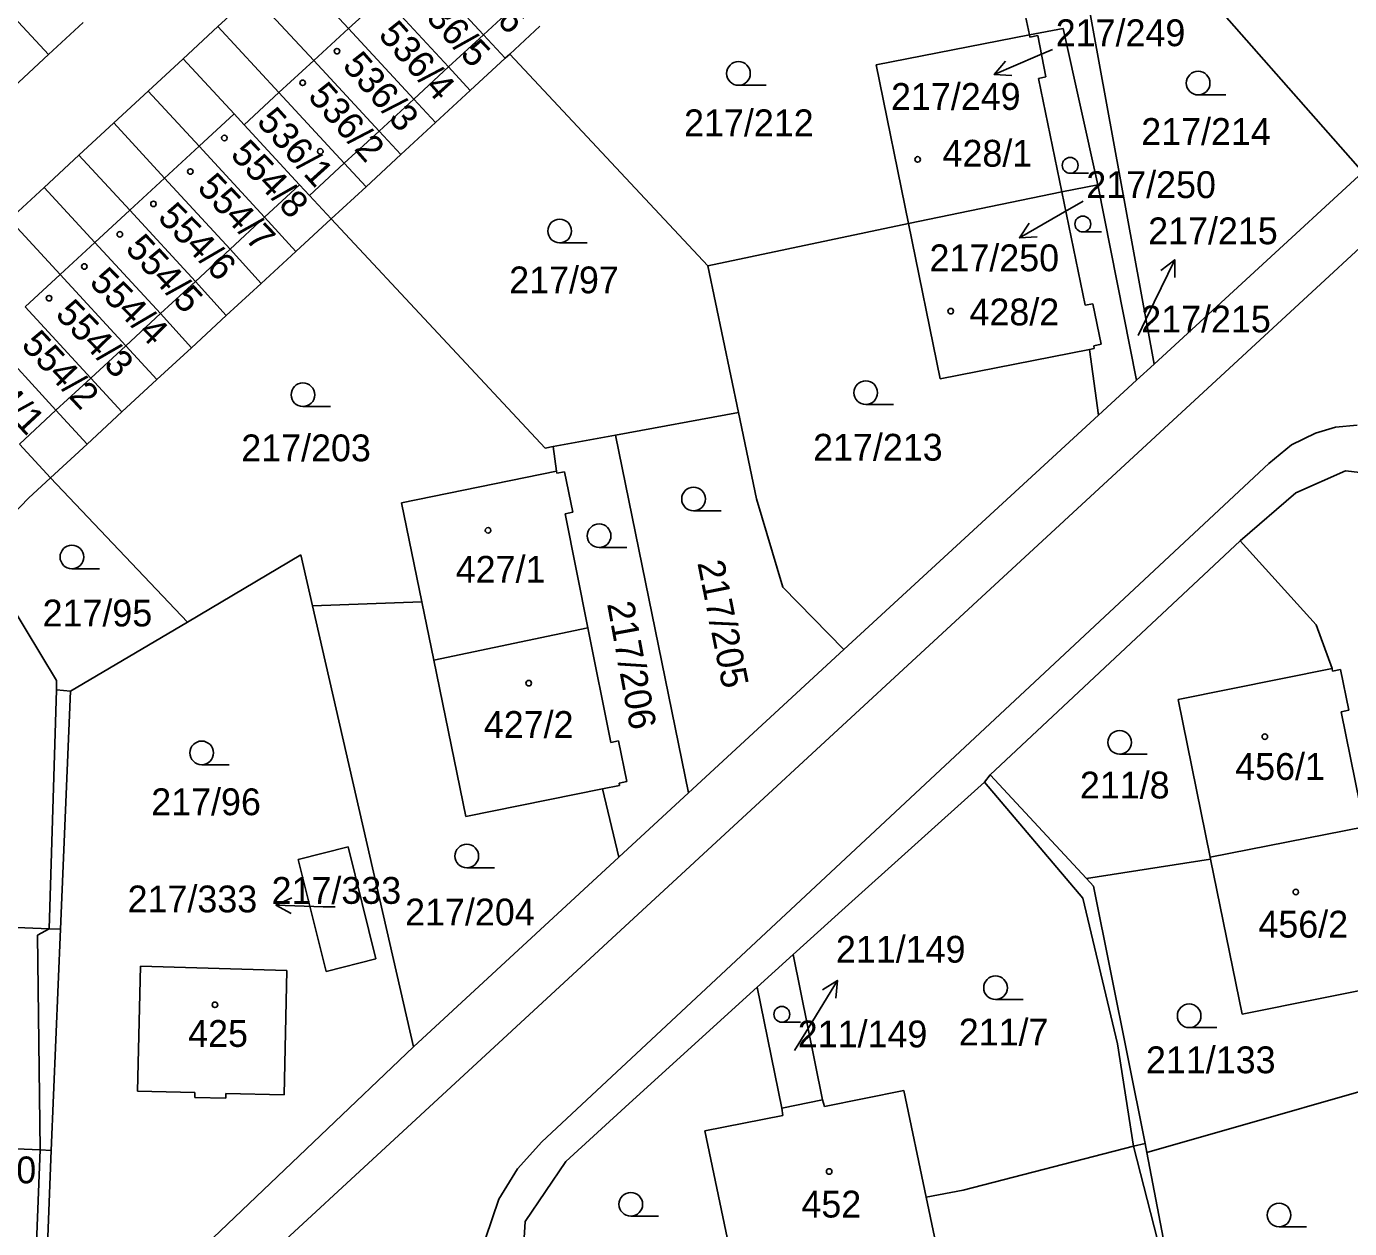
# Model space of a CAD drawing. Extents: x -735249 to -729401, y -1124843 to -1121828.
# Drawn here: x -733271.5 to -733187.6, y -1123306 to -1123229.8 of the extents above; entities that cross this region are included whole.
import ezdxf

# ---------------------------------------------------------------- set-up
doc = ezdxf.new("R2010")
doc.units = 0
for name, color, linetype in [('Vrstva 1', 7, 'Continuous'), ('Vrstva 16', 7, 'Continuous'), ('Vrstva 18', 7, 'Continuous'), ('Vrstva 19', 7, 'Continuous'), ('Vrstva 25', 7, 'Continuous'), ('Vrstva 4', 7, 'Continuous')]:
    doc.layers.add(name, color=color, linetype=linetype)

msp = doc.modelspace()

# ---------------------------------------------------------------- linework, layer by layer
at = {"layer": 'Vrstva 1'}
for points in [[(-733254.97, -1123225.7), (-733251.09, -1123229.88)], [(-733246.68, -1123225.81), (-733242.54, -1123230.29)], [(-733198.55, -1123225.62), (-733186.77, -1123238.99)], [(-733259.38, -1123229.77), (-733257.18, -1123227.74)], [(-733257.18, -1123227.74), (-733253.29, -1123231.92)], [(-733248.88, -1123227.85), (-733244.74, -1123232.33)], [(-733204.31, -1123227.55), (-733200.01, -1123251.17)], [(-733273.42, -1123227.98), (-733270.11, -1123231.54)], [(-733267.91, -1123229.51), (-733270.11, -1123231.54)], [(-733208.22, -1123228.82), (-733207.91, -1123230.3)], [(-733261.58, -1123231.81), (-733259.38, -1123229.77)], [(-733259.38, -1123229.77), (-733255.5, -1123233.95)], [(-733251.09, -1123229.88), (-733246.95, -1123234.36)], [(-733242.54, -1123230.29), (-733241.16, -1123231.78)], [(-733240.87, -1123231.52), (-733238.96, -1123229.75)], [(-733217.62, -1123232.2), (-733207.91, -1123230.3)], [(-733207.91, -1123230.3), (-733205.77, -1123229.88)], [(-733207.91, -1123230.3), (-733207.88, -1123230.44)], [(-733207.88, -1123230.44), (-733207.38, -1123230.33)], [(-733207.38, -1123230.33), (-733206.86, -1123232.95)], [(-733205.77, -1123229.88), (-733203.58, -1123239.8)], [(-733270.11, -1123231.54), (-733272.32, -1123233.58)], [(-733263.8, -1123233.86), (-733261.58, -1123231.81)], [(-733261.58, -1123231.81), (-733258.35, -1123235.3)], [(-733253.29, -1123231.92), (-733249.15, -1123236.4)], [(-733241.16, -1123231.78), (-733243.37, -1123233.81)], [(-733241.16, -1123231.78), (-733240.87, -1123231.52)], [(-733240.87, -1123231.52), (-733228.31, -1123244.94)], [(-733244.74, -1123232.33), (-733243.37, -1123233.81)], [(-733217.62, -1123232.2), (-733215.57, -1123242.25)], [(-733206.86, -1123232.95), (-733207.34, -1123233.05)], [(-733243.37, -1123233.81), (-733245.57, -1123235.85)], [(-733207.34, -1123233.05), (-733205.86, -1123240.24)], [(-733176.48, -1123234.11), (-733421.95, -1123460.73)], [(-733265.98, -1123235.88), (-733263.8, -1123233.86)], [(-733263.8, -1123233.86), (-733260.57, -1123237.35)], [(-733255.5, -1123233.95), (-733251.36, -1123238.43)], [(-733246.95, -1123234.36), (-733245.57, -1123235.85)], [(-733258.35, -1123235.3), (-733257.7, -1123235.99)], [(-733268.19, -1123237.92), (-733265.98, -1123235.88)], [(-733265.98, -1123235.88), (-733262.76, -1123239.37)], [(-733257.7, -1123235.99), (-733254.19, -1123239.8)], [(-733245.57, -1123235.85), (-733247.78, -1123237.88)], [(-733249.15, -1123236.4), (-733247.78, -1123237.88)], [(-733270.4, -1123239.97), (-733268.19, -1123237.92)], [(-733268.19, -1123237.92), (-733264.96, -1123241.41)], [(-733260.57, -1123237.35), (-733256.41, -1123241.85)], [(-733247.78, -1123237.88), (-733249.98, -1123239.92)], [(-733251.36, -1123238.43), (-733249.98, -1123239.92)], [(-733262.76, -1123239.37), (-733258.6, -1123243.88)], [(-733200.01, -1123251.17), (-733186.77, -1123238.99)], [(-733272.59, -1123242), (-733270.4, -1123239.97)], [(-733270.4, -1123239.97), (-733267.18, -1123243.46)], [(-733254.19, -1123239.8), (-733253.56, -1123240.47)], [(-733253.56, -1123240.47), (-733252.19, -1123241.95)], [(-733249.98, -1123239.92), (-733252.19, -1123241.95)], [(-733215.57, -1123242.25), (-733205.86, -1123240.24)], [(-733205.86, -1123240.24), (-733203.58, -1123239.8)], [(-733205.86, -1123240.24), (-733204.37, -1123247.44)], [(-733203.58, -1123239.8), (-733201.11, -1123252.18)], [(-733272.59, -1123242), (-733269.37, -1123245.49)], [(-733264.96, -1123241.41), (-733260.8, -1123245.92)], [(-733256.41, -1123241.85), (-733254.44, -1123244.03)], [(-733254.44, -1123244.03), (-733252.19, -1123241.95)], [(-733238.61, -1123256.49), (-733252.19, -1123241.95)], [(-733215.57, -1123242.25), (-733228.31, -1123244.94)], [(-733215.57, -1123242.25), (-733213.56, -1123252.1)], [(-733267.18, -1123243.46), (-733263.02, -1123247.97)], [(-733258.6, -1123243.88), (-733256.63, -1123246.05)], [(-733256.63, -1123246.05), (-733254.44, -1123244.03)], [(-733269.37, -1123245.49), (-733265.21, -1123250)], [(-733228.31, -1123244.94), (-733226.36, -1123254.24)], [(-733260.8, -1123245.92), (-733258.84, -1123248.08)], [(-733258.84, -1123248.08), (-733256.63, -1123246.05)], [(-733271.59, -1123247.54), (-733267.43, -1123252.05)], [(-733263.02, -1123247.97), (-733261.05, -1123250.13)], [(-733203.88, -1123247.34), (-733204.37, -1123247.44)], [(-733203.35, -1123249.91), (-733203.88, -1123247.34)], [(-733261.05, -1123250.13), (-733258.84, -1123248.08)], [(-733273.8, -1123249.57), (-733269.64, -1123254.09)], [(-733265.21, -1123250), (-733263.24, -1123252.15)], [(-733263.24, -1123252.15), (-733261.05, -1123250.13)], [(-733204.1, -1123250.24), (-733213.56, -1123252.1)], [(-733203.8, -1123250.18), (-733204.1, -1123250.24)], [(-733204.1, -1123250.24), (-733203.53, -1123254.41)], [(-733203.83, -1123250.01), (-733203.35, -1123249.91)], [(-733203.8, -1123250.18), (-733203.83, -1123250.01)], [(-733201.11, -1123252.18), (-733200.01, -1123251.17)], [(-733267.43, -1123252.05), (-733265.46, -1123254.2)], [(-733265.46, -1123254.2), (-733263.24, -1123252.15)], [(-733203.53, -1123254.41), (-733201.11, -1123252.18)], [(-733269.64, -1123254.09), (-733267.67, -1123256.24)], [(-733267.67, -1123256.24), (-733265.46, -1123254.2)], [(-733226.36, -1123254.24), (-733234.15, -1123255.67)], [(-733226.36, -1123254.24), (-733225.21, -1123259.71)], [(-733219.67, -1123269.26), (-733203.53, -1123254.41)], [(-733191.3, -1123256.29), (-733189.77, -1123255.54)], [(-733189.77, -1123255.54), (-733188.51, -1123255.16)], [(-733188.51, -1123255.16), (-733187.12, -1123255.04)], [(-733271.96, -1123256.24), (-733269.99, -1123258.38)], [(-733269.99, -1123258.38), (-733267.67, -1123256.24)], [(-733238.12, -1123256.4), (-733238.61, -1123256.49)], [(-733234.15, -1123255.67), (-733238.12, -1123256.4)], [(-733238.12, -1123256.4), (-733237.9, -1123257.95)], [(-733234.15, -1123255.67), (-733229.53, -1123278.36)], [(-733192.72, -1123257.46), (-733191.3, -1123256.29)], [(-733247.73, -1123259.96), (-733237.9, -1123257.95)], [(-733238.83, -1123300.49), (-733192.72, -1123257.46)], [(-733237.9, -1123257.95), (-733237.87, -1123258.09)], [(-733237.87, -1123258.09), (-733237.39, -1123257.99)], [(-733237.39, -1123257.99), (-733236.87, -1123260.56)], [(-733191.01, -1123259.33), (-733187.87, -1123257.94)], [(-733187.87, -1123257.94), (-733183.98, -1123258.38)], [(-733269.99, -1123258.38), (-733271.38, -1123259.66)], [(-733269.99, -1123258.38), (-733261.3, -1123267.52)], [(-733271.38, -1123259.66), (-733273.39, -1123261.75)], [(-733225.21, -1123259.71), (-733223.55, -1123265.31)], [(-733194.55, -1123262.38), (-733191.01, -1123259.33)], [(-733247.73, -1123259.96), (-733246.44, -1123266.25)], [(-733236.87, -1123260.56), (-733237.36, -1123260.66)], [(-733237.36, -1123260.66), (-733235.91, -1123267.9)], [(-733269.6, -1123271.23), (-733274.59, -1123262.99)], [(-733210.4, -1123277.22), (-733194.55, -1123262.38)], [(-733194.55, -1123262.38), (-733189.72, -1123267.69)], [(-733261.3, -1123267.52), (-733254.11, -1123263.27)], [(-733254.11, -1123263.27), (-733253.37, -1123266.49)], [(-733223.55, -1123265.31), (-733219.67, -1123269.26)], [(-733253.37, -1123266.49), (-733246.44, -1123266.25)], [(-733253.37, -1123266.49), (-733246.96, -1123294.45)], [(-733246.44, -1123266.25), (-733245.68, -1123269.93)], [(-733268.71, -1123271.9), (-733261.3, -1123267.52)], [(-733245.68, -1123269.93), (-733235.91, -1123267.9)], [(-733235.91, -1123267.9), (-733234.45, -1123275.15)], [(-733189.72, -1123267.69), (-733188.71, -1123270.47)], [(-733229.53, -1123278.36), (-733219.67, -1123269.26)], [(-733245.68, -1123269.93), (-733243.65, -1123279.86)], [(-733188.71, -1123270.47), (-733198.48, -1123272.44)], [(-733188.71, -1123270.47), (-733188.68, -1123270.63)], [(-733188.68, -1123270.63), (-733188.19, -1123270.53)], [(-733188.19, -1123270.53), (-733187.65, -1123273.11)], [(-733269.61, -1123271.82), (-733269.6, -1123271.23)], [(-733268.71, -1123271.9), (-733269.61, -1123271.82)], [(-733269.35, -1123287), (-733268.71, -1123271.9)], [(-733198.48, -1123272.44), (-733196.44, -1123282.44)], [(-733187.65, -1123273.11), (-733188.15, -1123273.21)], [(-733188.15, -1123273.21), (-733186.67, -1123280.5)], [(-733234.45, -1123275.15), (-733233.96, -1123275.05)], [(-733233.96, -1123275.05), (-733233.43, -1123277.64)], [(-733210.76, -1123277.68), (-733210.4, -1123277.22)], [(-733210.4, -1123277.22), (-733204.28, -1123283.79)], [(-733234.98, -1123278.1), (-733243.65, -1123279.86)], [(-733233.9, -1123277.88), (-733234.98, -1123278.1)], [(-733234.98, -1123278.1), (-733233.94, -1123282.43)], [(-733233.43, -1123277.64), (-733233.93, -1123277.74)], [(-733233.93, -1123277.74), (-733233.9, -1123277.88)], [(-733219.8, -1123285.82), (-733210.76, -1123277.68)], [(-733233.94, -1123282.43), (-733229.53, -1123278.36)], [(-733196.44, -1123282.44), (-733186.67, -1123280.5)], [(-733254.28, -1123282.57), (-733251.11, -1123281.78)], [(-733251.11, -1123281.78), (-733249.36, -1123288.88)], [(-733246.96, -1123294.45), (-733233.94, -1123282.43)], [(-733196.44, -1123282.44), (-733196.42, -1123282.56)], [(-733252.51, -1123289.67), (-733254.28, -1123282.57)], [(-733204.28, -1123283.79), (-733196.42, -1123282.56)], [(-733196.42, -1123282.56), (-733194.42, -1123292.39)], [(-733204.28, -1123283.79), (-733203.84, -1123284.26)], [(-733203.84, -1123284.26), (-733200.58, -1123300.58)], [(-733219.8, -1123285.82), (-733222.68, -1123288.41)], [(-733270.08, -1123286.97), (-733279.37, -1123286.59)], [(-733270.08, -1123286.97), (-733269.35, -1123287)], [(-733269.35, -1123287), (-733269.95, -1123301.03)], [(-733249.36, -1123288.88), (-733252.51, -1123289.67)], [(-733222.89, -1123288.6), (-733225.17, -1123290.67)], [(-733222.68, -1123288.41), (-733222.89, -1123288.6)], [(-733222.89, -1123288.6), (-733221.03, -1123297.82)], [(-733264.48, -1123297.27), (-733264.28, -1123289.35)], [(-733264.28, -1123289.35), (-733255, -1123289.62)], [(-733255, -1123289.62), (-733255.17, -1123297.5)], [(-733225.17, -1123290.67), (-733233.3, -1123298.05)], [(-733225.17, -1123290.67), (-733223.61, -1123298.34)], [(-733194.42, -1123292.39), (-733184.63, -1123290.43)], [(-733246.96, -1123294.45), (-733270.56, -1123316.95)], [(-733180.65, -1123295.5), (-733200.47, -1123301.15)], [(-733260.83, -1123297.36), (-733264.48, -1123297.27)], [(-733260.84, -1123297.66), (-733260.83, -1123297.36)], [(-733255.17, -1123297.5), (-733258.86, -1123297.41)], [(-733258.86, -1123297.41), (-733258.86, -1123297.71)], [(-733220.9, -1123298.24), (-733215.87, -1123297.23)], [(-733215.87, -1123297.23), (-733214.46, -1123303.98)], [(-733258.86, -1123297.71), (-733260.84, -1123297.66)], [(-733233.3, -1123298.05), (-733237.31, -1123301.73)], [(-733223.61, -1123298.34), (-733221.03, -1123297.82)], [(-733223.55, -1123298.81), (-733223.61, -1123298.34)], [(-733221.03, -1123297.82), (-733220.9, -1123298.24)], [(-733228.49, -1123299.79), (-733223.55, -1123298.81)], [(-733226.02, -1123311.59), (-733228.49, -1123299.79)], [(-733279.88, -1123300.6), (-733270.64, -1123300.98)], [(-733238.83, -1123300.49), (-733240.37, -1123302.19)], [(-733201.3, -1123300.76), (-733212.12, -1123303.55)], [(-733201.3, -1123300.76), (-733200.58, -1123300.58)], [(-733200.58, -1123300.58), (-733200.47, -1123301.15)], [(-733270.64, -1123300.98), (-733269.95, -1123301.03)], [(-733269.95, -1123301.03), (-733270.56, -1123316.95)], [(-733237.31, -1123301.73), (-733239.88, -1123305.53)], [(-733200.47, -1123301.15), (-733198.27, -1123312.64)], [(-733240.37, -1123302.19), (-733241.55, -1123304.11)], [(-733241.55, -1123304.11), (-733242.41, -1123306.6)], [(-733214.46, -1123303.98), (-733212.12, -1123303.55)], [(-733214.46, -1123303.98), (-733213.4, -1123309.02)], [(-733239.88, -1123305.53), (-733240.16, -1123310.03)]]:
    msp.add_lwpolyline(points, dxfattribs=at)
at = {"layer": 'Vrstva 16'}
for points in [[(-733206.44, -1123231.21), (-733207.39, -1123231.62)], [(-733204.5, -1123240.84), (-733205.94, -1123241.67)], [(-733201.02, -1123249.36), (-733200, -1123247.25)], [(-733251.94, -1123285.59), (-733252.7, -1123285.57)], [(-733222.8, -1123294.69), (-733221.65, -1123292.81)]]:
    msp.add_lwpolyline(points, dxfattribs=at)
at = {"layer": 'Vrstva 25'}
for points in [[(-733207.39, -1123231.62), (-733210.141, -1123232.816)], [(-733209.024, -1123232.876), (-733210.141, -1123232.816), (-733209.423, -1123231.958)], [(-733226.36, -1123233.49), (-733224.61, -1123233.49)], [(-733197.21, -1123234.1), (-733195.46, -1123234.1)], [(-733205.33, -1123239.07), (-733204.157, -1123239.07)], [(-733205.94, -1123241.67), (-733208.543, -1123243.16)], [(-733207.427, -1123243.097), (-733208.543, -1123243.16), (-733207.924, -1123242.23)], [(-733204.52, -1123242.79), (-733203.347, -1123242.79)], [(-733237.7, -1123243.48), (-733235.95, -1123243.48)], [(-733200, -1123247.25), (-733198.695, -1123244.55)], [(-733199.58, -1123245.232), (-733198.695, -1123244.55), (-733198.68, -1123245.667)], [(-733253.98, -1123253.86), (-733252.23, -1123253.86)], [(-733218.29, -1123253.73), (-733216.54, -1123253.73)], [(-733229.21, -1123260.47), (-733227.46, -1123260.47)], [(-733235.2, -1123262.8), (-733233.45, -1123262.8)], [(-733268.63, -1123264.15), (-733266.88, -1123264.15)], [(-733260.4, -1123276.57), (-733258.65, -1123276.57)], [(-733202.19, -1123275.9), (-733200.44, -1123275.9)], [(-733243.59, -1123283.11), (-733241.84, -1123283.11)], [(-733254.716, -1123285.999), (-733255.698, -1123285.466), (-733254.681, -1123285.001)], [(-733252.7, -1123285.57), (-733255.698, -1123285.466)], [(-733221.65, -1123292.81), (-733220.087, -1123290.25)], [(-733221.035, -1123290.843), (-733220.087, -1123290.25), (-733220.182, -1123291.364)], [(-733210.06, -1123291.46), (-733208.31, -1123291.46)], [(-733223.61, -1123292.9), (-733222.437, -1123292.9)], [(-733197.78, -1123293.24), (-733196.03, -1123293.24)], [(-733233.19, -1123305.19), (-733231.44, -1123305.19)], [(-733192.08, -1123305.87), (-733190.33, -1123305.87)]]:
    msp.add_lwpolyline(points, dxfattribs=at)
for centre, radius in [((-733251.82, -1123231.33), 0.175), ((-733226.36, -1123232.74), 0.75), ((-733197.21, -1123233.35), 0.75), ((-733254, -1123233.33), 0.175), ((-733258.96, -1123236.83), 0.175), ((-733252.88, -1123237.68), 0.175), ((-733261.12, -1123238.96), 0.175), ((-733215, -1123238.19), 0.175), ((-733205.329, -1123238.568), 0.503), ((-733263.46, -1123241.01), 0.175), ((-733237.7, -1123242.73), 0.75), ((-733204.52, -1123242.288), 0.503), ((-733265.59, -1123242.94), 0.175), ((-733267.84, -1123244.98), 0.175), ((-733270.08, -1123246.99), 0.175), ((-733212.9, -1123247.81), 0.175), ((-733218.29, -1123252.98), 0.75), ((-733253.98, -1123253.11), 0.75), ((-733229.21, -1123259.72), 0.75), ((-733235.2, -1123262.05), 0.75), ((-733242.24, -1123261.71), 0.175), ((-733268.63, -1123263.4), 0.75), ((-733239.66, -1123271.4), 0.175), ((-733202.19, -1123275.15), 0.75), ((-733192.98, -1123274.79), 0.175), ((-733260.4, -1123275.82), 0.75), ((-733243.59, -1123282.36), 0.75), ((-733191.02, -1123284.64), 0.175), ((-733210.06, -1123290.71), 0.75), ((-733259.56, -1123291.79), 0.175), ((-733223.61, -1123292.397), 0.503), ((-733197.78, -1123292.49), 0.75), ((-733220.61, -1123302.36), 0.175), ((-733233.19, -1123304.44), 0.75), ((-733192.08, -1123305.12), 0.75)]:
    msp.add_circle(centre, radius, dxfattribs=at)
at = {"layer": 'Vrstva 4'}
for points in [[(-733248.88, -1123227.85), (-733251.09, -1123229.88)], [(-733242.54, -1123230.29), (-733240.33, -1123228.26)], [(-733251.09, -1123229.88), (-733253.29, -1123231.92)], [(-733244.74, -1123232.33), (-733242.54, -1123230.29)], [(-733253.29, -1123231.92), (-733255.5, -1123233.95)], [(-733246.95, -1123234.36), (-733244.74, -1123232.33)], [(-733257.7, -1123235.99), (-733255.5, -1123233.95)], [(-733249.15, -1123236.4), (-733246.95, -1123234.36)], [(-733260.57, -1123237.35), (-733258.35, -1123235.3)], [(-733251.36, -1123238.43), (-733249.15, -1123236.4)], [(-733262.76, -1123239.37), (-733260.57, -1123237.35)], [(-733253.56, -1123240.47), (-733251.36, -1123238.43)], [(-733264.96, -1123241.41), (-733262.76, -1123239.37)], [(-733256.41, -1123241.85), (-733254.19, -1123239.8)], [(-733267.18, -1123243.46), (-733264.96, -1123241.41)], [(-733258.6, -1123243.88), (-733256.41, -1123241.85)], [(-733269.37, -1123245.49), (-733267.18, -1123243.46)], [(-733260.8, -1123245.92), (-733258.6, -1123243.88)], [(-733271.59, -1123247.54), (-733269.37, -1123245.49)], [(-733263.02, -1123247.97), (-733260.8, -1123245.92)], [(-733265.21, -1123250), (-733263.02, -1123247.97)], [(-733267.43, -1123252.05), (-733265.21, -1123250)], [(-733269.64, -1123254.09), (-733267.43, -1123252.05)], [(-733271.96, -1123256.24), (-733269.64, -1123254.09)], [(-733269.61, -1123271.82), (-733270.08, -1123286.97)], [(-733210.76, -1123277.68), (-733204.53, -1123285.03)], [(-733204.53, -1123285.03), (-733202.33, -1123294.26)], [(-733270.08, -1123286.97), (-733270.81, -1123287.38)], [(-733270.81, -1123287.38), (-733270.64, -1123300.98)], [(-733202.33, -1123294.26), (-733201.3, -1123300.76)], [(-733201.3, -1123300.76), (-733198.27, -1123312.64)], [(-733270.64, -1123300.98), (-733271.29, -1123317.62)]]:
    msp.add_lwpolyline(points, dxfattribs=at)

# ---------------------------------------------------------------- texts
at = {"layer": 'Vrstva 16'}
for s, p in [('217/249', (-733216.687, -1123235.05)), ('217/215', (-733200.38, -1123243.57)), ('217/250', (-733214.247, -1123245.28)), ('217/333', (-733265.098, -1123285.93)), ('211/149', (-733220.18, -1123289.12)), ('217/260', (-733279.11, -1123303.11))]:
    msp.add_text(s, height=1.7, dxfattribs=at).set_placement(p)
at = {"layer": 'Vrstva 18'}
for s, p in [('217/249', (-733206.24, -1123231.01)), ('217/212', (-733229.81, -1123236.72)), ('217/214', (-733200.82, -1123237.27)), ('217/250', (-733204.3, -1123240.64)), ('217/97', (-733240.9, -1123246.68)), ('217/215', (-733200.82, -1123249.16)), ('217/203', (-733257.89, -1123257.33)), ('217/213', (-733221.63, -1123257.29)), ('217/95', (-733270.49, -1123267.8)), ('211/8', (-733204.71, -1123278.71)), ('217/96', (-733263.6, -1123279.77)), ('217/333', (-733255.968, -1123285.39)), ('217/204', (-733247.5, -1123286.76)), ('211/149', (-733222.6, -1123294.49)), ('211/7', (-733212.39, -1123294.37)), ('211/133', (-733200.52, -1123296.13))]:
    msp.add_text(s, height=1.7, dxfattribs=at).set_placement(p)
for s, rotation, p in [('217/205', 281.40224, (-733228.975, -1123263.766)), ('217/206', 280.40223, (-733234.698, -1123266.36))]:
    msp.add_text(s, height=1.7, rotation=rotation, dxfattribs=at).set_placement(p)
at = {"layer": 'Vrstva 19'}
for s, rotation, p in [('536/6', 314.4025, (-733244.848, -1123226.292)), ('536/5', 313.30249, (-733247.098, -1123228.338)), ('536/4', 311.80248, (-733249.258, -1123230.345)), ('536/3', 311.30248, (-733251.538, -1123232.288)), ('536/2', 311.60248, (-733253.728, -1123234.236)), ('536/1', 312.10248, (-733256.978, -1123235.844)), ('554/8', 313.80249, (-733258.648, -1123237.945)), ('554/7', 313.50249, (-733260.748, -1123240.047)), ('554/6', 314.3025, (-733263.258, -1123241.933)), ('554/5', 312.90249, (-733265.308, -1123243.9)), ('554/4', 314.6025, (-733267.588, -1123246.051)), ('554/3', 314.0025, (-733269.748, -1123248.074)), ('554/2', 313.10249, (-733271.908, -1123250.009)), ('554/1', 312.90249, (-733275.328, -1123251.61))]:
    msp.add_text(s, height=1.7, rotation=rotation, dxfattribs=at).set_placement(p)
for s, p in [('428/1', (-733213.42, -1123238.65)), ('428/2', (-733211.71, -1123248.71)), ('427/1', (-733244.29, -1123265.03)), ('427/2', (-733242.51, -1123274.87)), ('456/1', (-733194.86, -1123277.53)), ('456/2', (-733193.39, -1123287.53)), ('425', (-733261.26, -1123294.46)), ('452', (-733222.37, -1123305.28))]:
    msp.add_text(s, height=1.7, dxfattribs=at).set_placement(p)

doc.saveas('drawing.dxf')
